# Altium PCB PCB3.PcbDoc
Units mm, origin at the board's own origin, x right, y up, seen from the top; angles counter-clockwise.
Board outline 101.6 x 53.34 mm, 4 copper layers (TOP, GND, SIG, BOTTOM), stack 1.586 mm thick; 108 components, 243 nets, 903 pads, 0 vias.
Unrouted connection lines stored in the file: 26.
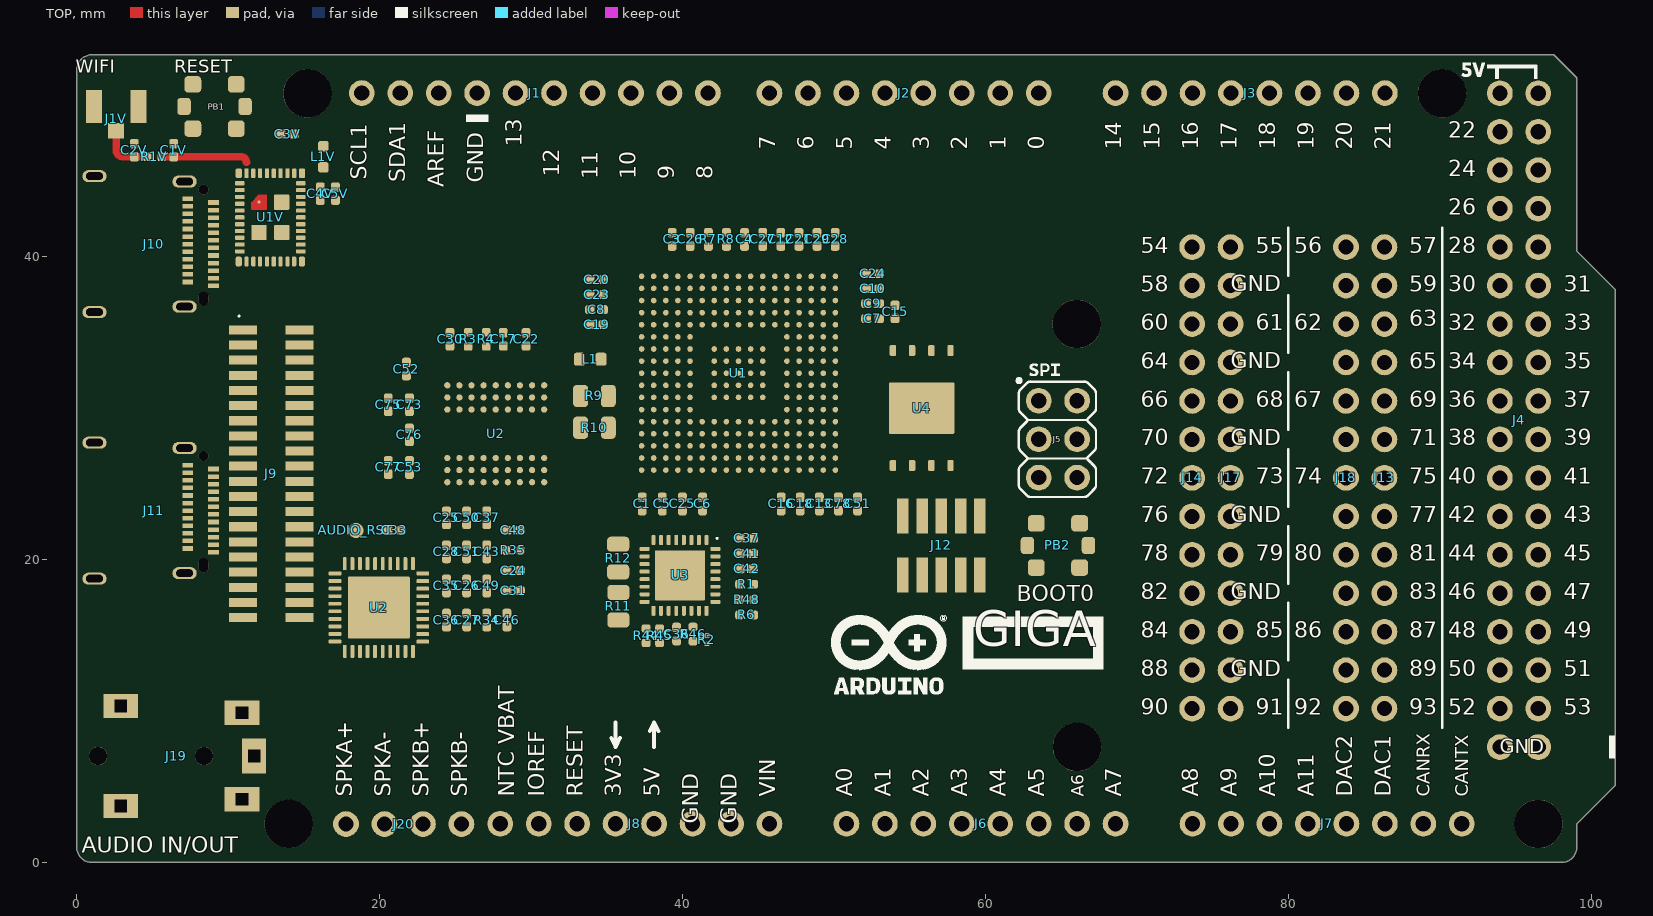
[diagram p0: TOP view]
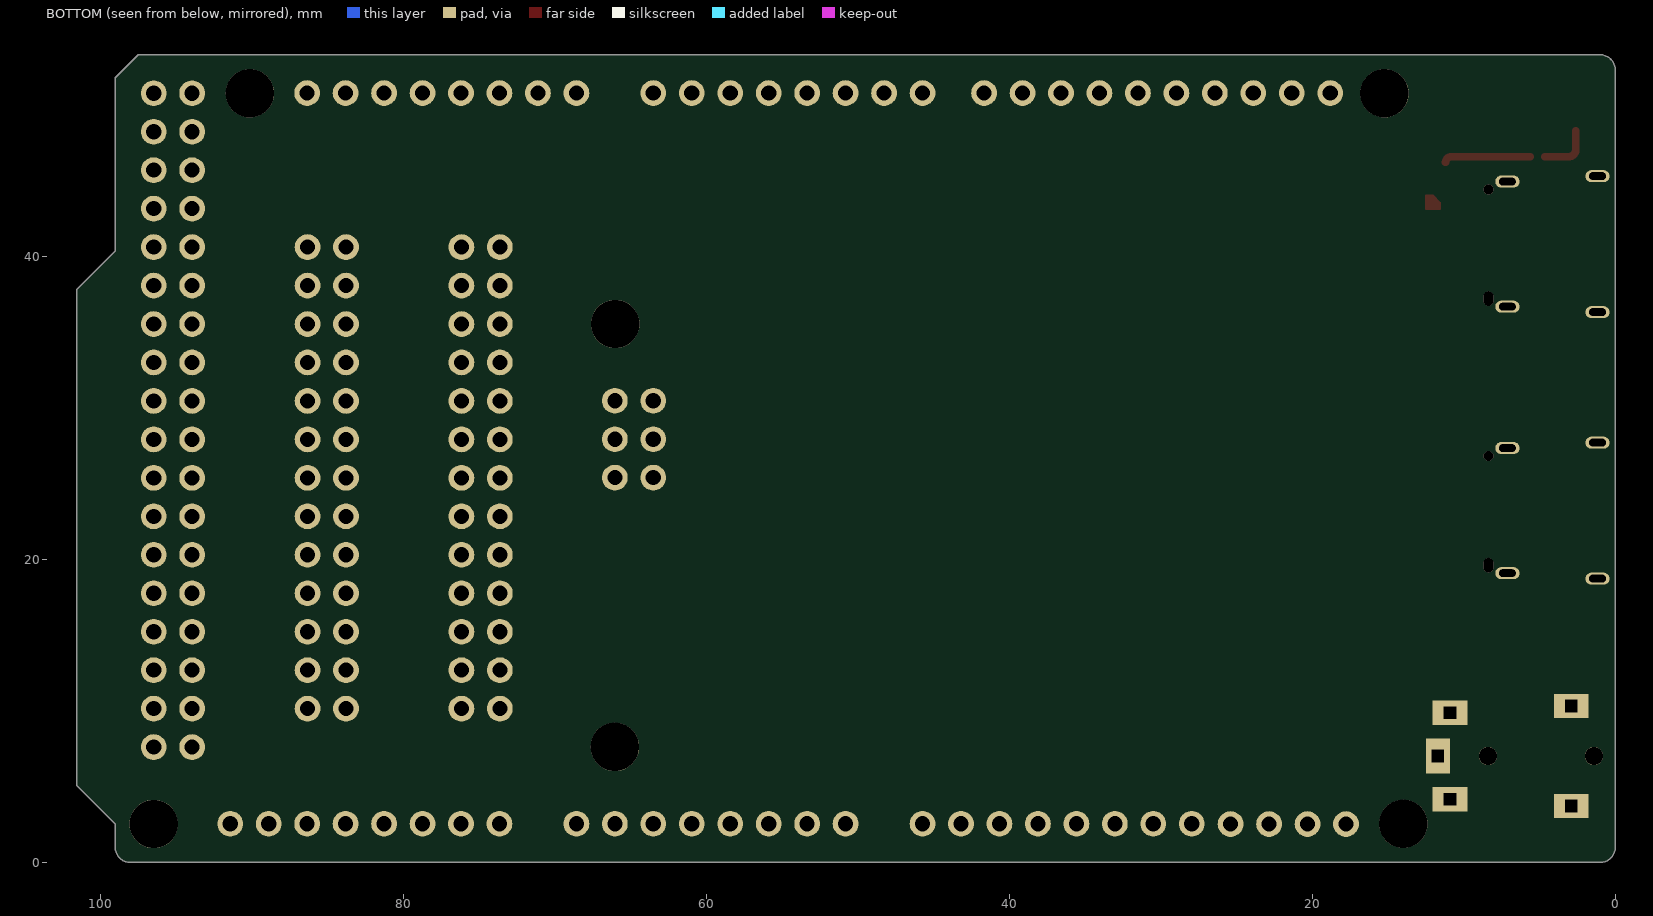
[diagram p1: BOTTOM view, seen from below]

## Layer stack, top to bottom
Top Solder: solder mask 0.0102, Solder Resist, Dk 3.5
TOP: signal copper 0.018
Dielectric 1: prepreg 0.14, PP-014, Dk 4.2
GND: signal copper 0.035
Dielectric2: core 1.2, FR-4, Dk 4.8
SIG: signal copper 0.035
Dielectric3: prepreg 0.14, PP-014, Dk 4.2
BOTTOM: signal copper 0.018
Bottom Solder: solder mask 0.0102, Solder Resist, Dk 3.5

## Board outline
0,1 0,52.34 cw(c1,52.34) 1,53.34 97.536,53.34 99.06,51.816 99.06,40.386 101.6,37.846 101.6,5.08 99.06,2.54 99.06,1 cw(c98.06,1) 98.06,0 1,0 cw(c1,1)

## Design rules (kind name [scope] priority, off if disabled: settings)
BoardOutlineClearance Silks [(OnLayer('Top Overlay') OR OnLayer('Bottom Overlay'))] p1: gap=0.1 ignorepadtopadclearanceinfootprint=FALSE
BoardOutlineClearance [All] p2: gap=0.3 ignorepadtopadclearanceinfootprint=FALSE
Clearance COPPER_0.3mm [All] p1: gap=0.127 ignorepadtopadclearanceinfootprint=FALSE except(0.3: Arc-Fill Arc-Poly Arc-Region Track-Fill Track-Poly Track-Region SMDPad-Fill SMDPad-Poly SMDPad-Region THPad-Fill THPad-Poly THPad-Region Via-Fill Via-Poly Via-Region Fill-Fill Fill-Poly Fill-Region Poly-Poly Poly-Region Region-Region)
Clearance "Generic clearance 0.127mm" [All] p2: gap=0.127 ignorepadtopadclearanceinfootprint=FALSE
ComponentClearance [All] p1: gap=0.2 collisioncheckmode=3 verticalgap=0 showdistances=TRUE
DiffPairsRouting USB [InDifferentialPairClass('USB')] p1: maxlimit=0.254 minlimit=0.15 mostfreqgap=0.254 toplayer_maxgap=0.15 toplayer_prefgap=0.15 toplayer_minwidth=0.15 toplayer_maxwidth=0.21 toplayer_prefwidth=0.2 midlayer2_mingap=0.24 midlayer2_maxgap=0.24 midlayer2_prefgap=0.24 midlayer2_minwidth=0.15 midlayer2_maxwidth=0.15 midlayer2_prefwidth=0.15 bottomlayer_maxgap=0.15 bottomlayer_prefgap=0.15 bottomlayer_minwidth=0.15 bottomlayer_maxwidth=0.21 bottomlayer_prefwidth=0.2 impedanceprofiledriven=TRUE impedanceprofileid={E6B00C31-4C8E-439C-824F-D2B2CDC26F9C} impedanceprofilevalue=90.000000 maxuncoupledlength=12.7
Height [All] p1: minheight=0 maxheight=30 prefheight=12.7
HoleSize [All] p1: absolutevalues=TRUE maxlimit=20 minlimit=0.3 maxpercent=80.000 minpercent=20.000
HoleToHoleClearance [All] p1: gap=0.25 allowstackedmicrovias=FALSE
MinimumAnnularRing [All] p1: minimumring=0.15
PlaneConnect [All] p1: pad.planeconnectstyle=Relief pad.reliefexpansion=0.508 pad.reliefentries=4 pad.reliefconductorwidth=0.254 pad.reliefairgap=0.254 via.planeconnectstyle=Direct via.reliefexpansion=0.508 via.reliefentries=4 via.reliefconductorwidth=0.254 via.reliefairgap=0.254
PolygonConnect [All] p1: thpad.connectstyle=Relief thpad.reliefconductorwidth=0.2 thpad.reliefentries=4 thpad.polygonreliefangle="90 Angle" thpad.airgapwidth=0.254 smdpad.connectstyle=Relief smdpad.reliefconductorwidth=0.2 smdpad.reliefentries=4 smdpad.polygonreliefangle="90 Angle" smdpad.airgapwidth=0.254 via.connectstyle=Direct via.reliefconductorwidth=0.254 via.reliefentries=4 via.polygonreliefangle="90 Angle" via.airgapwidth=0.254
RoomDefinition AUDIO [InComponentClass('AUDIO')] p1: confinementstyle=ConfineIn formatcopy=TRUE lockcomponents=FALSE outline 102.7,0.5 179.2,0.5 179.2,30 102.7,30
RoomDefinition Wifi [InComponentClass('Wifi')] p2: confinementstyle=ConfineIn formatcopy=TRUE lockcomponents=FALSE outline -40.4,-40.4 10.4,-40.4 10.4,-15 -40.4,-15
RoomDefinition TOP [InComponentClass('TOP')] p3: confinementstyle=ConfineIn formatcopy=TRUE lockcomponents=FALSE outline 102.7,1.5 112.4,1.5 112.4,12.5 102.7,12.5
RoomDefinition HEADERS [InComponentClass('HEADERS')] p4: confinementstyle=ConfineIn formatcopy=TRUE lockcomponents=FALSE outline 103.6,3.6 145.6,3.6 145.6,51.6 103.6,51.6
RoomDefinition STM32H747 [InComponentClass('STM32H747')] p5: confinementstyle=ConfineIn formatcopy=TRUE lockcomponents=FALSE outline 57.6,-10.4 61.6,-10.4 61.6,-6.4 57.6,-6.4
RoutingVias StandardVias [All] p1: holewidth=0.2 width=0.4 viastyle="Through Hole" minholewidth=0.2 minwidth=0.4 maxholewidth=0.2 maxwidth=0.4
SMDToCorner [All] p1: distance=39370
SilkToSilkClearance [All] p1: silktosilkclearance=0.2
SilkToSolderMaskClearance [IsPad] p1: minsilkscreentomaskgap=0.15 clearancetoexposedcopper=TRUE
SolderMaskExpansion VIAtented [IsVia] p1: expansion=0.102 istentingtop=TRUE
SolderMaskExpansion [All] p2: expansion=0.05 istentingtop=FALSE
UnRoutedNet [All] p1: checkbadconnections=TRUE
ViasUnderSMD [All] p1: allowed=FALSE
Width StandardTraces [All] p1: maxlimit=5 minlimit=0.127 preferedwidth=0.15
21 further rules are at their usual default settings.

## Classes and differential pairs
component class AUDIO: J19
net class "50 ohm": NetC1V_1 NetC2V_1
component class Wifi: C1V C2V C3V C4V C5V J1V L1V R1V R18 U1V
component class TOP: PB1 PB2
component class HEADERS: J1 J2 J3 J4 J5 J6 J7 J8 J13 J14 J17 J18 J20

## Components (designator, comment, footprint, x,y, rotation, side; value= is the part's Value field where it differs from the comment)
AUDIO_RST "CMP-018-0005-A.3" TP-1.00MM 18.437,21.925 r180 top
C1 "CBR04C220F5GAC" CAP-0402 37.34,23.675 r90 top value=22pF
C1V "DNP" CAP-0402 6.4,47.035 r90 top
C2V "DNP" CAP-0402 3.8,47.035 r90 top
C3 "GRM155R60J106ME05D" CAP-0402 39.319,41.145 r270 top value=10µF
C3V "GRM155R60J225KE95D" CAP-0402 13.919,48.102 r180 top value=2.2µF
C4 "GRM155R60J225KE95D" CAP-0402 44.104,41.145 r270 top value=2.2µF
C4V "GRM155R60J475ME47D" CAP-0402 16.084,44.167 r270 top value=4.7µF
C5 "GRM155R60J225KE95D" CAP-0402 38.67,23.675 r90 top value=2.2µF
C5V "GRM155R60J475ME47D" CAP-0402 17.084,44.167 r270 top value=4.7µF
C6 "GRM155R60J225KE95D" CAP-0402 41.33,23.675 r90 top value=2.2µF
C7 "GRM155R61H104KE19D" CAP-0402 52.557,35.913 r0 top value=100nF
C8 "GRM155R61H104KE19D" CAP-0402 34.325,36.51 r0 top value=100nF
C9 "GRM155R61H104KE19D" CAP-0402 52.557,36.903 r0 top value=100nF
C10 "GRM155R61H104KE19D" CAP-0402 52.557,37.893 r0 top value=100nF
C12 "CBR04C220F5GAC" CAP-0402 46.496,41.145 r270 top value=22pF
C13 "GRM155R61H104KE19D" CAP-0402 49.041,23.675 r270 top value=100nF
C15 "GRM155R61H104KE19D" CAP-0402 54.039,36.36 r90 top value=100nF
C16 "GRM155R61H104KE19D" CAP-0402 46.52,23.675 r270 top value=100nF
C17 "GRM155R61H104KE19D" CAP-0402 28.169,34.545 r90 top value=100nF
C18 "GRM155R61H104KE19D" CAP-0402 47.781,23.675 r270 top value=100nF
C19 "GRM155R61H104KE19D" CAP-0402 34.325,35.52 r0 top value=100nF
C20 "GRM155R61H104KE19D" CAP-0402 34.325,38.49 r0 top value=100nF
C21 "GRM155R61H104KE19D" CAP-0402 47.692,41.145 r270 top value=100nF
C22 "GRM155R61H104KE19D" CAP-0402 29.669,34.545 r90 top value=100nF
C23 "GRM155R61H104KE19D" CAP-0402 34.325,37.5 r0 top value=100nF
C24 "GRM155R61H104KE19D" CAP-0402 52.557,38.883 r0 top value=100nF
C24 "C0402C105K8PACTU" CAP-0402 28.835,19.28 r180 top value=1µF
C25 "GRM155R60J225KE95D" CAP-0402 40,23.675 r90 top value=2.2µF
C25 "C0402C104K4RACTU" CAP-0402 24.416,22.76 r90 top value=100nF
C26 "GRM155R60J225KE95D" CAP-0402 40.515,41.145 r270 top value=2.2µF
C26 "C0402C104K4RACTU" CAP-0402 25.746,18.26 r90 top value=100nF
C27 "GRM155R60J225KE95D" CAP-0402 45.3,41.145 r270 top value=2.2µF
C27 "C0402C104K4RACTU" CAP-0402 25.746,16.01 r90 top value=100nF
C28 "GRM155R61H104KE19D" CAP-0402 50.085,41.145 r270 top value=100nF
C28 "C0402C105K8PACTU" CAP-0402 24.416,20.51 r90 top value=1µF
C29 "GRM155R61H104KE19D" CAP-0402 48.889,41.145 r270 top value=100nF
C30 "GRM155R60J106ME05D" CAP-0402 24.648,34.545 r270 top value=10µF
C31 "C0402C105K8PACTU" CAP-0402 28.835,17.95 r180 top value=1µF
C33 "C0402C105K8PACTU" CAP-0402 20.977,21.925 r180 top value=1µF
C35 "C0402C104K4RACTU" CAP-0402 24.416,18.26 r90 top value=100nF
C36 "GRM155R61H104KE19D" CAP-0402 39.615,15.085 r90 top value=100nF
C36 "C0402C104K4RACTU" CAP-0402 24.416,16.01 r90 top value=100nF
C37 "GRM155R61H104KE19D" CAP-0402 44.235,21.41 r180 top value=100nF
C37 "C0402C104K4RACTU" CAP-0402 27.076,22.76 r90 top value=100nF
C41 "GRM155R61H104KE19D" CAP-0402 44.235,20.397 r180 top value=100nF
C42 "GRM155R61H104KE19D" CAP-0402 44.235,19.383 r180 top value=100nF
C43 "C0402C104K4RACTU" CAP-0402 27.076,20.51 r90 top value=100nF
C46 "GRM1555C1H151FA01D" CAP-0402 28.406,16.01 r90 top value=150pF
C48 "C0402C104K4RACTU" CAP-0402 28.835,21.94 r180 top value=100nF
C49 "C0402C105K8PACTU" CAP-0402 27.076,18.26 r90 top value=1µF
C50 "GRM1555C1H151FA01D" CAP-0402 25.746,22.76 r90 top value=150pF
C51 "GRM155R61H104KE19D" CAP-0402 51.563,23.675 r270 top value=100nF
C51 "C0402C104K4RACTU" CAP-0402 25.746,20.51 r90 top value=100nF
C52 "GRM155R61H104KE19D" CAP-0402 21.772,32.585 r90 top value=100nF
C53 "GRM155R61H104KE19D" CAP-0402 21.972,26.085 r270 top value=100nF
C73 "GRM155R61H104KE19D" CAP-0402 21.972,30.23 r90 top value=100nF
C75 "GRM155R61H104KE19D" CAP-0402 20.572,30.23 r270 top value=100nF
C76 "GRM155R61H104KE19D" CAP-0402 21.972,28.24 r90 top value=100nF
C77 "GRM155R61H104KE19D" CAP-0402 20.572,26.085 r90 top value=100nF
C78 "GRM155R61H104KE19D" CAP-0402 50.302,23.675 r270 top value=100nF
J1 "HEADER TH 2.54mm VERT. 1x010POS" "PIN HEADER 2.54mm VERT. 1x10POS" 30.252,50.813 r0 top
J1V "U.FL-R-SMT-1(60)" U.FL-R-SMT-1(60)-1 2.6,49.925 r0 top
J2 "HEADER TH 2.54mm VERT. 1x008POS" "PIN HEADER 2.54mm VERT. 1x8POS" 54.636,50.813 r0 top
J3 "HEADER TH 2.54mm VERT. 1x008POS" "PIN HEADER 2.54mm VERT. 1x8POS" 77.496,50.813 r0 top
J4 "HEADER TH 2.54mm VERT. 2x018POS" "PIN HEADER 2.54mm VERT. 2x6POS" 95.25,29.209 r270 top
J5 "HEADER TH 2.54mm VERT. 2x003POS" "HEADER TH 2.54mm VERT. 2x003POS-Footprint-1" 64.796,27.953 r270 top
J6 "HEADER TH 2.54mm VERT. 1x008POS" "PIN HEADER 2.54mm VERT. 1x8POS" 59.716,2.553 r0 top
J7 "HEADER TH 2.54mm VERT. 1x008POS" "PIN HEADER 2.54mm VERT. 1x8POS" 82.576,2.553 r0 top
J8 "HEADER TH 2.54mm VERT. 1x008POS" "PIN HEADER 2.54mm VERT. 1x8POS" 36.856,2.553 r0 top
J9 "2-1734248-0" 2-1734248-0-Footprint-1 12.884,25.67 r0 top (schematic designator J4)
J10 "12401598E4#2A" 12401598E4#2A 5.1,40.835 r270 top (schematic designator J1)
J11 "12401598E4#2A" 12401598E4#2A 5.1,23.235 r270 top (schematic designator J1)
J12 "FTSH-105-01-F-DV" FTSH-105-01-F-DV-Footprint-1 57.1,20.933 r180 top
J13 "HEADER TH 2.54mm VERT. 1x013POS" "PIN HEADER 2.54mm VERT. 1x13POS" 86.36,25.399 r270 top
J14 "HEADER TH 2.54mm VERT. 1x013POS" "PIN HEADER 2.54mm VERT. 1x13POS" 73.66,25.399 r270 top
J17 "HEADER TH 2.54mm VERT. 1x013POS" "PIN HEADER 2.54mm VERT. 1x13POS" 76.2,25.399 r270 top
J18 "HEADER TH 2.54mm VERT. 1x013POS" "PIN HEADER 2.54mm VERT. 1x13POS" 83.82,25.399 r270 top
J19 "54-00174" 54-00174-Footprint-1 11.71,7.03 r0 top
J20 "HEADER TH 2.54mm VERT. 1x004POS" "PIN HEADER 2.54mm VERT. 1x4POS-Footprint-1" 21.59,2.539 r0 top
L1 "FBMJ1608HM180NTR" L-0603 33.91,33.24 r0 top
L1V "LQM18PN2R2MGHD" FP-LQM18PN_GH-IPC_C 16.284,46.602 r270 top value=2.2uH
PB1 "PTS820J25KSMTRLFS" C&K_PTS820_NO_HOLES-1 9.1,49.925 r180 top
PB2 "PTS820J25KSMTRLFS" C&K_PTS820_NO_HOLES-1 64.796,20.933 r180 top
R1 "CRCW0402100KFKEDC" RES-0402 44.235,18.37 r0 top value=100k
R1V "CRCW04020000Z0EDC" RES-0402 5.125,46.6 r180 top value=0
R2 "RC0201FR-078K06L" RES-0201 41.615,14.715 r270 top value=8.06k
R3 "CRCW04020000Z0EDC" RES-0402 25.848,34.545 r90 top value=0
R4 "CRCW0402100KFKEDC" RES-0402 27.048,34.545 r90 top value=100k
R6 "CRCW0402100KFKEDC" RES-0402 44.235,16.343 r180 top value=100k
R7 "CRCW04020000Z0EDC" RES-0402 41.711,41.145 r270 top value=0
R8 "CRCW04020000Z0EDC" RES-0402 42.908,41.145 r270 top value=0
R9 "CRCW08050000Z0EB" RES-0805 34.185,30.81 r180 top value=0
R10 "CRCW08050000Z0EB" RES-0805 34.185,28.71 r180 top value=0
R11 "CRCW08050000Z0EB" RES-0805 35.769,16.92 r90 top value=0
R12 "CRCW08050000Z0EB" RES-0805 35.751,20.101 r270 top value=0
R34 "CRCW04022K00JNED" RES-0402 27.076,16.01 r90 top value=2k
R35 "CRCW04022K00JNED" RES-0402 28.835,20.61 r180 top value=2k
R44 "CRCW04020000Z0EDC" RES-0402 37.6,14.97 r270 top value=0
R45 "CRCW04020000Z0EDC" RES-0402 38.492,14.97 r270 top value=0
R46 "CRCW040210K0FKED" RES-0402 40.7,15.085 r270 top value=10k
R48 "CRCW0402100KFKEDC" RES-0402 44.235,17.357 r0 top value=100k
U1 "STM32H747XIH6" STM32H747XIH6-Footprint-1 43.7,32.31 r270 top
U1V "LBEE5KL1DX-883" LBEE5KL1DX-883 12.784,42.602 r270 top
U2 "AS4C4M16SA-6BIN" AS4C4M16SA-7BCN-Footprint-1 27.669,28.31 r0 top
U2 "CS42L52-CNZ" QFN127P600-8N 19.951,16.835 r90 top
U3 "USB3320C-EZK-TR" USB3320C-EZK-Footprint-1 39.838,18.958 r180 top
U4 "MX25L12833FZ2I-10G" WSON8-1 55.8,30.01 r180 top

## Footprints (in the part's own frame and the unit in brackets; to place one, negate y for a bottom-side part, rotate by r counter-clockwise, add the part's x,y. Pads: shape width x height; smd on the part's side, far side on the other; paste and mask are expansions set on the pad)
2-1734248-0-Footprint-1 [mm]
  rect 1.85x0.6 smd: 1(-1.9,9.5) 2(-1.9,8.5) 3(-1.9,7.5) 4(-1.9,6.5) 5(-1.9,5.5) 6(-1.9,4.5) 7(-1.9,3.5) 8(-1.9,2.5) 9(-1.9,1.5) 10(-1.9,0.5) 11(-1.9,-0.5) 12(-1.9,-1.5) 13(-1.9,-2.5) 14(-1.9,-3.5) 15(-1.9,-4.5) 16(-1.9,-5.5) 17(-1.9,-6.5) 18(-1.9,-7.5) 19(-1.9,-8.5) 20(-1.9,-9.5) 21(1.825,-9.5) 22(1.825,-8.5) 23(1.825,-7.5) 24(1.825,-6.5) 25(1.825,-5.5) 26(1.825,-4.5) 27(1.825,-3.5) 28(1.825,-2.5) 29(1.825,-1.5) 30(1.825,-0.5) 31(1.825,0.5) 32(1.825,1.5) 33(1.825,2.5) 34(1.825,3.5) 35(1.825,4.5) 36(1.825,5.5) 37(1.825,6.5) 38(1.825,7.5) 39(1.825,8.5) 40(1.825,9.5)
  silkscreen extent -2.21,10.36 -2.11,10.46, body extent -2.4,-13.7 2.45,13.7, height 5.63
54-00174-Footprint-1 [mm]
  rect 1.6x2.3 hole 0.8 square unplated: 1(0,0)
  rect 2.3x1.6 hole 0.8 square unplated: 2(-0.8,2.85) 3(-0.8,-2.85) 4(-8.8,-3.3) 4(-8.8,3.3)
  round 1.2 hole 1.2 unplated mask+0.2: NC1(-3.3,0) NC2(-10.3,0)
  body extent -14.74,-3.5 0.26,3.6, height 6.13
12401598E4#2A [mm]
  oval 1x1.8 on Top Paste: 0(-4.499,-3.932) 0(-4.131,2.023) 0(4.131,2.026) 0(4.461,-3.925)
  round 0.65 hole 0.65 unplated mask+0.05: 0(-3.6,3.27)
  oval 0.95x0.65 hole 0.65 slot 0.95 at 0 deg unplated mask+0: 0(3.6,3.27)
  rect 0.3x0.7 smd mask+0.04: A1(-2.75,3.93) A2(-2.25,3.93) A3(-1.75,3.93) A4(-1.25,3.93) A5(-0.75,3.93) A6(-0.25,3.93) A7(0.25,3.93) A8(0.75,3.93) A9(1.25,3.93) A10(1.75,3.93) B1(2.5,2.23) B2(2,2.23) B3(1.5,2.23) B4(1,2.23) B5(0.5,2.23) B6(0,2.23) B7(-0.5,2.23) B8(-1,2.23) B9(-1.5,2.23) B10(-2,2.23) B11(-2.5,2.23) B12(-3,2.23)
  rect 0.3x0.7 smd mask+0.03: A11(2.25,3.93) A12(2.75,3.93)
  oval 0.8x1.6 hole 0.5 slot 1.1 at 90 deg: "SHIELD 1"(-4.13,2.02) "SHIELD 2"(4.13,2.02) "SHIELD 3"(-4.49,-3.93) "SHIELD 4"(4.49,-3.93)
  body extent -4.6,-6.3 4.6,4.25, height 3.3
AS4C4M16SA-7BCN-Footprint-1 [mm]
  round 0.41 smd: A1(-3.2,-3.2) A2(-3.2,-2.4) A3(-3.2,-1.6) A7(-3.2,1.6) A8(-3.2,2.4) A9(-3.2,3.2) B1(-2.4,-3.2) B2(-2.4,-2.4) B3(-2.4,-1.6) B7(-2.4,1.6) B8(-2.4,2.4) B9(-2.4,3.2) C1(-1.6,-3.2) C2(-1.6,-2.4) C3(-1.6,-1.6) C7(-1.6,1.6) C8(-1.6,2.4) C9(-1.6,3.2) D1(-0.8,-3.2) D2(-0.8,-2.4) D3(-0.8,-1.6) D7(-0.8,1.6) D8(-0.8,2.4) D9(-0.8,3.2) E1(0,-3.2) E2(0,-2.4) E3(0,-1.6) E7(0,1.6) E8(0,2.4) E9(0,3.2) F1(0.8,-3.2) F2(0.8,-2.4) F3(0.8,-1.6) F7(0.8,1.6) F8(0.8,2.4) F9(0.8,3.2) G1(1.6,-3.2) G2(1.6,-2.4) G3(1.6,-1.6) G7(1.6,1.6) G8(1.6,2.4) G9(1.6,3.2) H1(2.4,-3.2) H2(2.4,-2.4) H3(2.4,-1.6) H7(2.4,1.6) H8(2.4,2.4) H9(2.4,3.2) J1(3.2,-3.2) J2(3.2,-2.4) J3(3.2,-1.6) J7(3.2,1.6) J8(3.2,2.4) J9(3.2,3.2)
  body extent -4,-4 4,4, height 1.15
C&K_PTS820_NO_HOLES-1 [mm]
  rrect49% 0.89x1.12 smd: 5(-2.015,0) 6(2.015,0)
  rrect46% 1.11x1.09 smd: PAD(-1.434,1.46) PAD(-1.434,-1.46) PAD(1.434,1.46) PAD(1.434,-1.46)
  body extent -2.25,-1.45 2.25,1.45, height 2
CAP-0402 [mm] "Chip Capacitor, 2-Leads, Body  0402 (in) 1005 (mm), IPC Medium Density"
  rrect52% 0.63x0.58 smd mask+0: 1(-0.435,0) 2(0.435,0)
  body extent -0.5,-0.25 0.5,0.25, height 0.5
FP-LQM18PN_GH-IPC_C [mm]
  rrect50% 0.7x0.7 smd: 1(-0.7,0) 2(0.7,0)
  body extent -0.8,-0.4 0.8,0.4, height 1
FTSH-105-01-F-DV-Footprint-1 [mm]
  rect 0.76x2.3 smd: 1(-2.54,-1.95) 2(-2.54,1.95) 3(-1.27,-1.95) 4(-1.27,1.95) 5(0,-1.95) 6(0,1.95) 7(1.27,-1.95) 8(1.27,1.95) 9(2.54,-1.95) 10(2.54,1.95)
  body extent -3.17,-2.92 3.17,2.92, height 5.98
"HEADER TH 2.54mm VERT. 2x003POS-Footprint-1" [mm]
  round 1.7 hole 1 mask+0.2: 1(-2.54,-1.27) 2(-2.54,1.27) 3(0,-1.27) 4(0,1.27) 5(2.54,-1.27) 6(2.54,1.27)
L-0603 [mm] "Chip Inductor - Body 0603 imperial,1.6x0.8mm, IPC High Density"
  rrect51% 0.75x0.87 smd mask+0: 1(-0.71,0) 2(0.71,0)
  body extent -0.8,-0.4 0.8,0.4, height 0.8
LBEE5KL1DX-883 [mm]
  rrect50% 0.28x0.64 smd mask+0.05: 1(-2.25,-2.015) 2(-1.8,-2.015) 3(-1.35,-2.015) 4(-0.9,-2.015) 5(-0.45,-2.015) 6(0,-2.015) 7(0.45,-2.015) 8(0.9,-2.015) 9(1.35,-2.015) 10(1.8,-2.015) 11(2.25,-2.015) 22(2.25,2.015) 23(1.8,2.015) 24(1.35,2.015) 25(0.9,2.015) 26(0.45,2.015) 27(0,2.015) 28(-0.45,2.015) 29(-0.9,2.015) 30(-1.35,2.015) 31(-1.8,2.015) 32(-2.25,2.015)
  rrect50% 0.64x0.4 smd mask+0.05: 12(2.915,-2.087) 21(2.915,2.087) 33(-2.915,2.087) 42(-2.915,-2.087)
  rrect50% 0.64x0.28 smd mask+0.05: 13(2.915,-1.575) 14(2.915,-1.125) 15(2.915,-0.675) 16(2.915,-0.225) 17(2.915,0.225) 18(2.915,0.675) 19(2.915,1.125) 20(2.915,1.575) 34(-2.915,1.575) 35(-2.915,1.125) 36(-2.915,0.675) 37(-2.915,0.225) 38(-2.915,-0.225) 39(-2.915,-0.675) 40(-2.915,-1.125) 41(-2.915,-1.575)
  round 0.2 smd paste+0 mask+0.05: 43(-1,-0.75)
  rrect10% 1x1 smd mask+0.05: 44(1,-0.75) 45(-1,0.75) 46(1,0.75)
  TOP region: -1.485,-0.765 -1.496,-0.748 -1.5,-0.729 -1.5,-0.729 -1.5,-0.3 -1.496,-0.281 -1.485,-0.265 -1.469,-0.254 -1.45,-0.25 -1.45,-0.25 -0.55,-0.25 -0.531,-0.254 -0.515,-0.265 -0.504,-0.281 -0.5,-0.3 -0.5,-0.3 -0.5,-1.2 -0.504,-1.219 -0.515,-1.235 -0.531,-1.246 -0.55,-1.25 -0.55,-1.25 -0.979,-1.25 -0.998,-1.246 -1.015,-1.235 -1.015,-1.235
  body extent -3.47,-2.57 3.48,2.58, height 1.1
"PIN HEADER 2.54mm VERT. 1x4POS-Footprint-1" [mm]
  round 1.7 hole 1 mask+0.2: 1(-3.81,0) 2(-1.27,0) 3(1.27,0) 4(3.81,0)
"PIN HEADER 2.54mm VERT. 1x8POS" [mm]
  round 1.7 hole 1 mask+0.2: 1(-8.89,0) 2(-6.35,0) 3(-3.81,0) 4(-1.27,0) 5(1.27,0) 6(3.81,0) 7(6.35,0) 8(8.89,0)
"PIN HEADER 2.54mm VERT. 1x10POS" [mm]
  round 1.7 hole 1 mask+0.2: 1(-11.43,0) 2(-8.89,0) 3(-6.35,0) 4(-3.81,0) 5(-1.27,0) 6(1.27,0) 7(3.81,0) 8(6.35,0) 9(8.89,0) 10(11.43,0)
"PIN HEADER 2.54mm VERT. 1x13POS" [mm]
  round 1.7 hole 1 mask+0.2: 1(-15.24,0) 2(-12.7,0) 3(-10.16,0) 4(-7.62,0) 5(-5.08,0) 6(-2.54,0) 7(0,0) 8(2.54,0) 9(5.08,0) 10(7.62,0) 11(10.16,0) 12(12.7,0) 13(15.24,0)
"PIN HEADER 2.54mm VERT. 2x6POS" [mm]
  round 1.7 hole 1 mask+0.2: 1(-21.59,-1.27) 2(-21.59,1.27) 3(-19.05,-1.27) 4(-19.05,1.27) 5(-16.51,-1.27) 6(-16.51,1.27) 7(-13.97,-1.27) 8(-13.97,1.27) 9(-11.43,-1.27) 10(-11.43,1.27) 11(-8.89,-1.27) 12(-8.89,1.27) 13(-6.35,-1.27) 14(-6.35,1.27) 15(-3.81,-1.27) 16(-3.81,1.27) 17(-1.27,-1.27) 18(-1.27,1.27) 19(1.27,-1.27) 20(1.27,1.27) 21(3.81,-1.27) 22(3.81,1.27) 23(6.35,-1.27) 24(6.35,1.27) 25(8.89,-1.27) 26(8.89,1.27) 27(11.43,-1.27) 28(11.43,1.27) 29(13.97,-1.27) 30(13.97,1.27) 31(16.51,-1.27) 32(16.51,1.27) 33(19.05,-1.27) 34(19.05,1.27) 35(21.59,-1.27) 36(21.59,1.27)
QFN127P600-8N [mm]
  rrect50% 0.85x0.25 smd mask+0.05: 1(-2.9,2.25) 2(-2.9,1.75) 3(-2.9,1.25) 4(-2.9,0.75) 5(-2.9,0.25) 6(-2.9,-0.25) 7(-2.9,-0.75) 8(-2.9,-1.25) 9(-2.9,-1.75) 10(-2.9,-2.25) 21(2.9,-2.25) 22(2.9,-1.75) 23(2.9,-1.25) 24(2.9,-0.75) 25(2.9,-0.25) 26(2.9,0.25) 27(2.9,0.75) 28(2.9,1.25) 29(2.9,1.75) 30(2.9,2.25)
  rrect50% 0.25x0.85 smd mask+0.05: 11(-2.25,-2.9) 12(-1.75,-2.9) 13(-1.25,-2.9) 14(-0.75,-2.9) 15(-0.25,-2.9) 16(0.25,-2.9) 17(0.75,-2.9) 18(1.25,-2.9) 19(1.75,-2.9) 20(2.25,-2.9) 31(2.25,2.9) 32(1.75,2.9) 33(1.25,2.9) 34(0.75,2.9) 35(0.25,2.9) 36(-0.25,2.9) 37(-0.75,2.9) 38(-1.25,2.9) 39(-1.75,2.9) 40(-2.25,2.9)
  rrect5% 4.1x4.1 smd paste-5 mask+0.05: 41(0,0)
  body extent -3,-3 3,3, height 1
RES-0201 [mm] "Chip Resistor, 2-Leads, Body 0201 (in) 0603 (mm) IPC Medium Density"
  rrect52% 0.31x0.34 smd mask+0: 1(-0.275,0) 2(0.275,0)
  body extent -0.3,-0.15 0.3,0.15, height 0.24
RES-0402 [mm] "Chip Resistor, 2-Leads, Body  0402 (in) 1005 (mm), IPC Medium Density"
  rrect51% 0.55x0.58 smd mask+0: 1(-0.475,0) 2(0.475,0)
  body extent -0.5,-0.25 0.5,0.25, height 0.34
RES-0805 [mm] "Chip Resistor - Body 0805 imperial, 2.0x1.2mm, IPC Medium Density"
  rrect51% 0.99x1.47 smd paste-1.47 mask+0: 1(-0.915,0) 2(0.915,0)
  body extent -1,-0.62 1,0.63, height 0.58
STM32H747XIH6-Footprint-1 [mm]
  round 0.37 smd: A1(-6.4,-6.4) A2(-6.4,-5.6) A3(-6.4,-4.8) A4(-6.4,-4) A5(-6.4,-3.2) A6(-6.4,-2.4) A7(-6.4,-1.6) A8(-6.4,-0.8) A9(-6.4,0) A10(-6.4,0.8) A11(-6.4,1.6) A12(-6.4,2.4) A13(-6.4,3.2) A14(-6.4,4) A15(-6.4,4.8) A16(-6.4,5.6) A17(-6.4,6.4) B1(-5.6,-6.4) B2(-5.6,-5.6) B3(-5.6,-4.8) B4(-5.6,-4) B5(-5.6,-3.2) B6(-5.6,-2.4) B7(-5.6,-1.6) B8(-5.6,-0.8) B9(-5.6,0) B10(-5.6,0.8) B11(-5.6,1.6) B12(-5.6,2.4) B13(-5.6,3.2) B14(-5.6,4) B15(-5.6,4.8) B16(-5.6,5.6) B17(-5.6,6.4) C1(-4.8,-6.4) C2(-4.8,-5.6) C3(-4.8,-4.8) C4(-4.8,-4) C5(-4.8,-3.2) C6(-4.8,-2.4) C7(-4.8,-1.6) C8(-4.8,-0.8) C9(-4.8,0) C10(-4.8,0.8) C11(-4.8,1.6) C12(-4.8,2.4) C13(-4.8,3.2) C14(-4.8,4) C15(-4.8,4.8) C16(-4.8,5.6) C17(-4.8,6.4) D1(-4,-6.4) D2(-4,-5.6) D3(-4,-4.8) D4(-4,-4) D5(-4,-3.2) D6(-4,-2.4) D7(-4,-1.6) D8(-4,-0.8) D9(-4,0) D10(-4,0.8) D11(-4,1.6) D12(-4,2.4) D13(-4,3.2) D14(-4,4) D15(-4,4.8) D16(-4,5.6) D17(-4,6.4) E1(-3.2,-6.4) E2(-3.2,-5.6) E3(-3.2,-4.8) E4(-3.2,-4) E5(-3.2,-3.2) E6(-3.2,-2.4) E7(-3.2,-1.6) E8(-3.2,-0.8) E9(-3.2,0) E10(-3.2,0.8) E11(-3.2,1.6) E12(-3.2,2.4) E13(-3.2,3.2) E14(-3.2,4) E15(-3.2,4.8) E16(-3.2,5.6) E17(-3.2,6.4) F1(-2.4,-6.4) F2(-2.4,-5.6) F3(-2.4,-4.8) F4(-2.4,-4) F5(-2.4,-3.2) F13(-2.4,3.2) F14(-2.4,4) F15(-2.4,4.8) F16(-2.4,5.6) F17(-2.4,6.4) G1(-1.6,-6.4) G2(-1.6,-5.6) G3(-1.6,-4.8) G4(-1.6,-4) G5(-1.6,-3.2) G7(-1.6,-1.6) G8(-1.6,-0.8) G9(-1.6,0) G10(-1.6,0.8) G11(-1.6,1.6) G13(-1.6,3.2) G14(-1.6,4) G15(-1.6,4.8) G16(-1.6,5.6) G17(-1.6,6.4) H1(-0.8,-6.4) H2(-0.8,-5.6) H3(-0.8,-4.8) H4(-0.8,-4) H5(-0.8,-3.2) H7(-0.8,-1.6) H8(-0.8,-0.8) H9(-0.8,0) H10(-0.8,0.8) H11(-0.8,1.6) H13(-0.8,3.2) H14(-0.8,4) H15(-0.8,4.8) H16(-0.8,5.6) H17(-0.8,6.4) J1(0,-6.4) J2(0,-5.6) J3(0,-4.8) J4(0,-4) J5(0,-3.2) J7(0,-1.6) J8(0,-0.8) J9(0,0) J10(0,0.8) J11(0,1.6) J13(0,3.2) J14(0,4) J15(0,4.8) J16(0,5.6) J17(0,6.4) K1(0.8,-6.4) K2(0.8,-5.6) K3(0.8,-4.8) K4(0.8,-4) K5(0.8,-3.2) K7(0.8,-1.6) K8(0.8,-0.8) K9(0.8,0) K10(0.8,0.8) K11(0.8,1.6) K13(0.8,3.2) K14(0.8,4) K15(0.8,4.8) K16(0.8,5.6) K17(0.8,6.4) L1(1.6,-6.4) L2(1.6,-5.6) L3(1.6,-4.8) L4(1.6,-4) L5(1.6,-3.2) L7(1.6,-1.6) L8(1.6,-0.8) L9(1.6,0) L10(1.6,0.8) L11(1.6,1.6) L13(1.6,3.2) L14(1.6,4) L15(1.6,4.8) L16(1.6,5.6) L17(1.6,6.4) M1(2.4,-6.4) M2(2.4,-5.6) M3(2.4,-4.8) M4(2.4,-4) M5(2.4,-3.2) M13(2.4,3.2) M14(2.4,4) M15(2.4,4.8) M16(2.4,5.6) M17(2.4,6.4) N1(3.2,-6.4) N2(3.2,-5.6) N3(3.2,-4.8) N4(3.2,-4) N5(3.2,-3.2) N6(3.2,-2.4) N7(3.2,-1.6) N8(3.2,-0.8) N9(3.2,0) N10(3.2,0.8) N11(3.2,1.6) N12(3.2,2.4) N13(3.2,3.2) N14(3.2,4) N15(3.2,4.8) N16(3.2,5.6) N17(3.2,6.4) P1(4,-6.4) P2(4,-5.6) P3(4,-4.8) P4(4,-4) P5(4,-3.2) P6(4,-2.4) P7(4,-1.6) P8(4,-0.8) P9(4,0) P10(4,0.8) P11(4,1.6) P12(4,2.4) P13(4,3.2) P14(4,4) P15(4,4.8) P16(4,5.6) P17(4,6.4) R1(4.8,-6.4) R2(4.8,-5.6) R3(4.8,-4.8) R4(4.8,-4) R5(4.8,-3.2) R6(4.8,-2.4) R7(4.8,-1.6) R8(4.8,-0.8) R9(4.8,0) R10(4.8,0.8) R11(4.8,1.6) R12(4.8,2.4) R13(4.8,3.2) R14(4.8,4) R15(4.8,4.8) R16(4.8,5.6) R17(4.8,6.4) T1(5.6,-6.4) T2(5.6,-5.6) T3(5.6,-4.8) T4(5.6,-4) T5(5.6,-3.2) T6(5.6,-2.4) T7(5.6,-1.6) T8(5.6,-0.8) T9(5.6,0) T10(5.6,0.8) T11(5.6,1.6) T12(5.6,2.4) T13(5.6,3.2) T14(5.6,4) T15(5.6,4.8) T16(5.6,5.6) T17(5.6,6.4) U1(6.4,-6.4) U2(6.4,-5.6) U3(6.4,-4.8) U4(6.4,-4) U5(6.4,-3.2) U6(6.4,-2.4) U7(6.4,-1.6) U8(6.4,-0.8) U9(6.4,0) U10(6.4,0.8) U11(6.4,1.6) U12(6.4,2.4) U13(6.4,3.2) U14(6.4,4) U15(6.4,4.8) U16(6.4,5.6) U17(6.4,6.4)
  body extent -7,-7 7,7, height 1.06
TP-1.00MM [mm]
  rrect100% 1x1 smd paste-2.54: X(0,0)
U.FL-R-SMT-1(60)-1 [mm]
  rect 1.05x2.2 smd paste-3: GND(-1.475,0) GND(1.475,0)
  rect 1.05x1 smd paste-3: SIG(0,-1.6)
  body extent -1.5,-1.55 1.5,1.55, height 1.25
USB3320C-EZK-Footprint-1 [mm]
  rrect54% 0.26x0.66 smd paste+0 mask+0: 1(-1.75,-2.335) 2(-1.25,-2.335) 3(-0.75,-2.335) 4(-0.25,-2.335) 5(0.25,-2.335) 6(0.75,-2.335) 7(1.25,-2.335) 8(1.75,-2.335) 17(1.75,2.335) 18(1.25,2.335) 19(0.75,2.335) 20(0.25,2.335) 21(-0.25,2.335) 22(-0.75,2.335) 23(-1.25,2.335) 24(-1.75,2.335)
  rrect54% 0.66x0.26 smd paste+0 mask+0: 9(2.335,-1.75) 10(2.335,-1.25) 11(2.335,-0.75) 12(2.335,-0.25) 13(2.335,0.25) 14(2.335,0.75) 15(2.335,1.25) 16(2.335,1.75) 25(-2.335,1.75) 26(-2.335,1.25) 27(-2.335,0.75) 28(-2.335,0.25) 29(-2.335,-0.25) 30(-2.335,-0.75) 31(-2.335,-1.25) 32(-2.335,-1.75)
  rrect3% 3.3x3.3 smd paste-3.3 mask+0: 33(0,0)
  silkscreen extent -2.5,-2.5 -2.4,-2.4, body extent -2.5,-2.5 2.5,2.5, height 0.85
WSON8-1 [mm]
  rrect52% 0.42x0.74 smd paste+0 mask+0: 1(-1.905,-3.795) 2(-0.635,-3.795) 3(0.635,-3.795) 4(1.905,-3.795) 5(1.905,3.795) 6(0.635,3.795) 7(-0.635,3.795) 8(-1.905,3.795)
  rrect3% 4.3x3.4 smd paste-4.3 mask+0: 9(0,0)
  body extent -3,-4 3,4, height 0.75

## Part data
AUDIO_RST: library part UT0013-A.2, "Test point 1.00mm"
C1 C12: library part C0028-A.9, "CAP CHIP 0402 22pF 50V C0G 1%", Case Code (Imperial)=0402, Case Code (Metric)=1005, Dielectric=C0G, Manufacturer=KEMET, Manufacturer 2=AVX, Manufacturer Part Number 2=04025U220FAT2A, Tolerance=1%, Voltage=50V
C1V C2V: library part UT0021-A.2, "DNP CAP 0402", Package=0402
C3 C30: library part C0091-A.8, "CAP CHIP 0402 10UF X5R 6.3V 20%", Case Code (Imperial)=0402, Case Code (Metric)=1005, Dielectric=X5R, Manufacturer=Murata, Tolerance=20%, Voltage=6.3V
C3V C4 C5 C6 C25 C26 C27: library part C0031-A.9, "CAP CHIP 0402 2.2uF 6.3V X5R 10%", Case Code (Imperial)=0402, Case Code (Metric)=1005, Dielectric=X5R, Manufacturer=Murata, Tolerance=10%, Voltage=6.3V
C4V C5V: library part C0037-A.9, "CAP CHIP 0402 4.7uF 6V3 X5R 20%", Case Code (Imperial)=0402, Case Code (Metric)=1005, Dielectric=X5R, Manufacturer=Murata, Tolerance=20%, Voltage=6.3V
C7 C8 C9 C10 C13 C15 C16 C17 C18 C19 C20 C21 C22 C23 C24 C28 C29 C36 C37 C41 C42 C51 C52 C53 C73 C75 C76 C77 C78: library part C0015-A.9, "CAP CHIP 0402 100nF 50V X5R 10%", Case Code (Imperial)=0402, Case Code (Metric)=1005, Dielectric=X5R, Manufacturer=Murata, Tolerance=10%, Voltage=50V
C24 C28 C31 C33 C49: library part C0017-A.9, "CAP CHIP 0402 1uF 10V X5R 10%", Case Code (Imperial)=0402, Case Code (Metric)=1005, Dielectric=X5R, Manufacturer=KEMET, Manufacturer 2=AVX, Manufacturer Part Number 2=GRM155R61A105KE15D, Tolerance=10%, Voltage=10V
C25 C26 C27 C35 C36 C37 C43 C48 C51: library part C0012-A.9, "CAP CHIP 0402 100nF 16V X7R 10%", Case Code (Imperial)=0402, Case Code (Metric)=1005, Dielectric=X7R, Manufacturer=KEMET, Manufacturer 2=AVX, Manufacturer Part Number 2=0402YC104KAT2A, Tolerance=10%, Voltage=16V
C46 C50: library part C0074-A.7, "CAP CHIP 0402 150PF 50V C0G 1%", Case Code (Imperial)=0402, Case Code (Metric)=1005, Dielectric=C0G, Manufacturer=Murata, Tolerance=1%, Voltage=50V
J1: library part J0169-A.5
J1V: library part J0042-A.4, "CONN Micro UFL NO PASTE", Manufacturer=Hirose
J2 J3 J6 J7 J8: library part J0171-A.2
J4: library part J0239-A.1
J5: library part J0240-A.2
J9: library part J0081-A.3, "CONN FPC VERT 20POS 1.00MM SMD", Contact Current Rating=1A, Flammability Rating="UL94 V-0", Housing Color=Black, Manufacturer="TE Connectivity", Max Operating Temperature=185°C, Min Operating Temperature=-4°C, Package Quantity=1000, Voltage Rating=125V
J10 J11: library part J0220-A.5, "CONN RCP USB3.1 TYPEC 24P SMD RA", Flammability Rating="UL94 V-0", Manufacturer="Amphenol ICC (Commercial Products)"
J12: library part J0089-A.6, "CONN HEADER SMD 10POS 2x5 1.27MM JTAG", Color=Black, Current Rating=1.75A, Manufacturer=Samtec, Max Operating Temperature=125°C, Min Operating Temperature=-55°C, Package Quantity=1
J13 J14 J17 J18: library part J0245-A.1
J19: library part J0244-A.1, "Conn Jack 4 POLES 3.5mm R/a", Manufacturer="Tensility International Corp"
J20: library part J0162-A.4
L1: library part I0004-A.3, "FERRITE SMD 0603 18 OHM 1A", Case Code (Imperial)=0603, Case Code (Metric)=1608, Current=1A, DC Resistance (DCR)=4mR, Manufacturer="Taiyo Yuden", Max DC Current=7.5A, Max Operating Temperature=125°C, Min Operating Temperature=-40°C, Package Quantity=1, Test Frequency=100MHz, Tolerance=30%
L1V: library part I0051-A.3, "IND FIXED SMD 0603 2.2uH, 20%,", DC Resistance (DCR)=250mR, Manufacturer=Murata, Max Operating Temperature=85°C, Min Operating Temperature=-40°C, Test Frequency=1MHz, Tolerance=20%
PB1 PB2: library part B0006-A.7, "PUSHBUTTON SMD PTS820 NO HOLES", Color=Black, Manufacturer=C&K, Max Operating Temperature=85°C, Min Operating Temperature=-40°C
R1 R4 R6 R48: library part R0001-A.8, "RES CHIP 0402 100K 1% 1/16W", Case Code (Imperial)=0402, Case Code (Metric)=1005, Manufacturer=Vishay, Manufacturer 2=Panasonic, Manufacturer Part Number 2=ERJ-2RKF1003X, Power=63mW, Tolerance=1%
R1V R3 R7 R8 R44 R45: library part R0000-A.8, "RES CHIP 0402 0R 1/16W", Case Code (Imperial)=0402, Case Code (Metric)=1005, Manufacturer=Vishay, Manufacturer 2=Panasonic, Manufacturer Part Number 2=ERJ-S020R00X, Power=63mW, Tolerance=J
R2: library part R0154-A.2, "RES CHIP 0201 8.06kR 1/20W 1%", Case Code (Imperial)=0201, Case Code (Metric)=0603, Manufacturer=Yageo, Power=50mW, Tolerance=1%
R9 R10 R11 R12: library part R0131-A.3, "RES CHIP 0805 0R 1/8W", Case Code (Imperial)=0805, Case Code (Metric)=2012, Manufacturer=Vishay, Power=125mW, Tolerance=J
R34 R35: library part R0166-A.4, "RES CHIP 0402 2K 5% 1/16W", Case Code (Imperial)=0402, Case Code (Metric)=1005, Manufacturer=Vishay, Manufacturer 2=Panasonic, Manufacturer Part Number 2=ERJ-2GEJ202X, Power=63mW, Tolerance=1%
R46: library part R0003-A.8, "RES CHIP 0402 10K 1% 1/16W", Case Code (Imperial)=0402, Case Code (Metric)=1005, Manufacturer=Vishay, Manufacturer 2=Panasonic, Manufacturer Part Number 2=ERJ-2RKF1002X, Power=63mW, Tolerance=1%
U1: library part U0020-A.5, "IC MCU Cortex M7 + Cortex M4", Manufacturer=STMicroelectronics
U1V: library part U0008-A.14, "MODULE WiFi 11b/g/n+BLUETOOTH 4.2 SHIELDED ULTRA SMALL LBEE5KL1DX", Case/Package=SMD/SMT, Current - Receiving=60mA, Current - Transmitting=370mA, Frequency=2.4GHz, Manufacturer=Murata, Max Operating Temperature=70°C, Min Operating Temperature=-30°C
U2: library part U0122-A.2, "IC SDRAM 64 Mb PC133 SDR", Case/Package=TFBGA, Frequency=166MHz, Manufacturer="Alliance Memory", Max Operating Temperature=85°C, Min Operating Temperature=-40°C
U2: library part U0053-A.4, "IC CODEC STER HDPN & SPKR 40QFN", Case/Package=QFN, Manufacturer="Cirrus Logic", Max Operating Temperature=85°C, Min Operating Temperature=-40°C, Operating Supply Voltage=2.5V, Package Quantity=50
U3: library part U0121-A.4, "IC TXRX USB 2.0 FLEXPWR 32QFN", Case/Package=QFN, Frequency=60MHz, Manufacturer=Microchip, Max Operating Temperature=85°C, Max Supply Voltage=2V, Min Operating Temperature=-40°C, Min Supply Voltage=1.6V, Operating Supply Current=18uA, Operating Supply Voltage=5.5V, Package Quantity=4000
U4: library part U0120-A.2, "IC FLASH S-NOR 128M", Manufacturer=Macronix

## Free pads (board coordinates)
  round 3.2 hole 3.2 unplated: MH1(96.52,2.54) MH2(15.24,50.8) MH3(90.17,50.8) MH4(13.996,2.553) MH5(66.04,35.56) MH6(66.066,7.633)

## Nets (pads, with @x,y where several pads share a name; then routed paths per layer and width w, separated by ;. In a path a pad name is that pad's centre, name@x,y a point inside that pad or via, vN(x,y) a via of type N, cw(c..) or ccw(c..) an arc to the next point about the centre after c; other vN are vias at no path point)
+1V8: U1V.36
+3V1: 
+3V1SW: 
+3V3: C3V.2 C4V.1 U1V.30
AIN2A: 
AIN2B: 
AIN3A: 
AIN3B: 
BLE_CTRL_DEVICE_WAKE: U1V.39
BLE_CTRL_HOST_WAKE: U1V.38
BLE_CTRL_ON: U1V.14
DSI_CK_N: 
DSI_CK_P: 
DSI_D0_N: 
DSI_D0_P: 
DSI_D1_N: 
DSI_D1_P: 
GND: C1V.2 C2V.2 C3V.1 C4V.2 C5V.2 J1V.GND U1V.1 U1V.12 U1V.19 U1V.21 U1V.29 U1V.32 U1V.33 U1V.35 U1V.40 U1V.42 U1V.43 U1V.44 U1V.45 U1V.46
HP/LINE_OUTA: 
HP/LINE_OUTB: 
HSU_D_N: 
HSU_D_P: 
MICBIAS: 
NetAUDIO_RST_X: 
NetC1_2: 
NetC1V_1: C1V.1 R1V.1 U1V.41 | length 5.8
  TOP w0.5: R1V.1 C1V.1 10.839,46.6 cw(c10.839,46.23) 11.209,46.23
NetC2V_1: C2V.1 J1V.SIG R1V.2 | length 3.6
  TOP w0.5: J1V.SIG 2.6,47.1 ccw(c3.1,47.1) 3.1,46.6 C2V.1 R1V.2
NetC5V_1: C5V.1 L1V.2 U1V.31
NetC12_2: 
NetC30_2: 
NetC31_1: 
NetC31_2: 
NetC33_1: 
NetC46_1: 
NetC48_1: 
NetC49_1: 
NetC50_1: 
NetL1_2: 
NetL1V_1: L1V.1 U1V.34
NetR2_1: 
NetR3_1: 
NetR4_2: 
NetR6_1: 
NetR7_1: 
NetR8_2: 
NetR9_1: 
NetR10_2: 
NetR12_1: 
NetR34_2: 
NetR35_2: 
NetR46_1: 
NetR46_2: 
NetU1_J1: 
NetU1_K1: 
NetU1V_2: U1V.2
NetU1V_3: U1V.3
NetU1V_4: U1V.4
NetU1V_5: U1V.5
NetU1V_8: U1V.8
NetU1V_9: U1V.9
NetU1V_10: U1V.10
NetU1V_11: U1V.11
NetU1V_20: U1V.20
NetU1V_22: U1V.22
NetU1V_23: U1V.23
NetU1V_24: U1V.24
NetU1V_25: U1V.25
NetU1V_26: U1V.26
NetU1V_37: U1V.37
NetU2_37: 
NetU3_26: 
PA0: 
PA1: 
PA2: 
PA3: 
PA4: 
PA5: 
PA6: 
PA7: 
PA8: 
PA9: 
PA10: 
PA11: 
PA12: 
PA13: 
PA14: 
PA15: 
PB0: 
PB1: 
PB2: 
PB3: 
PB4: 
PB5: 
PB6: 
PB7: 
PB8: 
PB9: 
PB10: 
PB11: 
PB12: 
PB13: 
PB14: 
PB15: 
PC0: 
PC1: 
PC2: 
PC3: 
PC4: 
PC5: 
PC6: 
PC7: 
PC8: 
PC9: 
PC10: 
PC11: 
PC12: 
PC13: 
PD0: 
PD1: 
PD2: 
PD3: 
PD4: 
PD5: 
PD6: 
PD7: 
PD8: 
PD9: 
PD10: 
PD11: 
PD12: 
PD13: 
PD14: 
PD15: 
PE0: 
PE1: 
PE2: 
PE3: 
PE4: 
PE5: 
PE6: 
PE7: 
PE8: 
PE9: 
PE10: 
PE11: 
PE12: 
PE13: 
PE14: 
PE15: 
PF0: 
PF1: 
PF2: 
PF3: 
PF4: 
PF5: 
PF6: 
PF7: 
PF8: 
PF9: 
PF10: 
PF11: 
PF12: 
PF13: 
PF14: 
PF15: 
PG0: 
PG1: 
PG2: 
PG3: 
PG4: 
PG5: 
PG6: 
PG7: 
PG8: 
PG9: 
PG10: 
PG11: 
PG12: 
PG13: 
PG14: 
PG15: 
PH2: 
PH3: 
PH4: 
PH5: 
PH6: 
PH7: 
PH8: 
PH9: 
PH10: 
PH11: 
PH12: 
PH13: 
PH14: 
PH15: 
PI0: 
PI1: 
PI2: 
PI3: 
PI4: 
PI5: 
PI6: 
PI7: 
PI8: 
PI9: 
PI10: 
PI11: 
PI12: 
PI13: 
PI14: 
PI15: 
PJ0: 
PJ1: 
PJ2: 
PJ3: 
PJ4: 
PJ5: 
PJ6: 
PJ7: 
PJ8: 
PJ9: 
PJ10: 
PJ11: 
PJ12: 
PJ13: 
PJ14: 
PJ15: 
PK0: 
PK1: 
PK2: 
PK3: 
PK4: 
PK5: 
PK6: 
PK7: 
SPKR/HP: 
USB0_D_N: 
USB0_D_P: 
VCAP_A7: 
VCAP_D17: 
VCAP_U11: 
WIFI_CTRL_HOST_WAKE: U1V.27
WIFI_CTRL_ON: U1V.28
pads on no net: "J10.SHIELD 1" "J10.SHIELD 2" "J10.SHIELD 3" "J10.SHIELD 4" "J11.SHIELD 1" "J11.SHIELD 2" "J11.SHIELD 3" "J11.SHIELD 4" AUDIO_RST.X C1.1 C1.2 C3.1 C3.2 C4.1 C4.2 C5.1 C5.2 C6.1 C6.2 C7.1 C7.2 C8.1 C8.2 C9.1 C9.2 C10.1 C10.2 C12.1 C12.2 C13.1 C13.2 C15.1 C15.2 C16.1 C16.2 C17.1 C17.2 C18.1 C18.2 C19.1 C19.2 C20.1 C20.2 C21.1 C21.2 C22.1 C22.2 C23.1 C23.2 C24.1 C24.2 C25.1 C25.2 C26.1 C26.2 C27.1 C27.2 C28.1 C28.2 C29.1 C29.2 C30.1 C30.2 C31.1 C31.2 C33.1 C33.2 C35.1 C35.2 C36.1 C36.2 C37.1 C37.2 C41.1 C41.2 C42.1 C42.2 C43.1 C43.2 C46.1 C46.2 C48.1 C48.2 C49.1 C49.2 C50.1 C50.2 C51.1 C51.2 C52.1 C52.2 C53.1 C53.2 C73.1 C73.2 C75.1 C75.2 C76.1 C76.2 C77.1 C77.2 C78.1 C78.2 J1.1 J1.2 J1.3 J1.4 J1.5 J1.6 J1.7 J1.8 J1.9 J1.10 J2.1 J2.2 J2.3 J2.4 J2.5 J2.6 J2.7 J2.8 J3.1 J3.2 J3.3 J3.4 J3.5 J3.6 J3.7 J3.8 J4.1 J4.2 J4.3 J4.4 J4.5 J4.6 J4.7 J4.8 J4.9 J4.10 J4.11 J4.12 J4.13 J4.14 J4.15 J4.16 J4.17 J4.18 J4.19 J4.20 J4.21 J4.22 J4.23 J4.24 J4.25 J4.26 J4.27 J4.28 J4.29 J4.30 J4.31 J4.32 J4.33 J4.34 J4.35 J4.36 J5.1 J5.2 J5.3 J5.4 J5.5 J5.6 J6.1 J6.2 J6.3 J6.4 J6.5 J6.6 J6.7 J6.8 J7.1 J7.2 J7.3 J7.4 J7.5 J7.6 J7.7 J7.8 J8.1 J8.2 J8.3 J8.4 J8.5 J8.6 J8.7 J8.8 J9.1 J9.2 J9.3 J9.4 J9.5 J9.6 J9.7 J9.8 J9.9 J9.10 J9.11 J9.12 J9.13 J9.14 J9.15 J9.16 J9.17 J9.18 J9.19 J9.20 J9.21 J9.22 J9.23 J9.24 J9.25 J9.26 J9.27 J9.28 J9.29 J9.30 J9.31 J9.32 J9.33 J9.34 J9.35 J9.36 J9.37 J9.38 J9.39 J9.40 J10.0 J10.A1 J10.A2 J10.A3 J10.A4 J10.A5 J10.A6 J10.A7 J10.A8 J10.A9 J10.A10 J10.A11 J10.A12 J10.B1 J10.B2 J10.B3 J10.B4 J10.B5 J10.B6 J10.B7 J10.B8 J10.B9 J10.B10 J10.B11 J10.B12 J11.0 J11.A1 J11.A2 J11.A3 J11.A4 J11.A5 J11.A6 J11.A7 J11.A8 J11.A9 J11.A10 J11.A11 J11.A12 J11.B1 J11.B2 J11.B3 J11.B4 J11.B5 J11.B6 J11.B7 J11.B8 J11.B9 J11.B10 J11.B11 J11.B12 J12.1 J12.2 J12.3 J12.4 J12.5 J12.6 J12.7 J12.8 J12.9 J12.10 J13.1 J13.2 J13.3 J13.4 J13.5 J13.6 J13.7 J13.8 J13.9 J13.10 J13.11 J13.12 J13.13 J14.1 J14.2 J14.3 J14.4 J14.5 J14.6 J14.7 J14.8 J14.9 J14.10 J14.11 J14.12 J14.13 J17.1 J17.2 J17.3 J17.4 J17.5 J17.6 J17.7 J17.8 J17.9 J17.10 J17.11 J17.12 J17.13 J18.1 J18.2 J18.3 J18.4 J18.5 J18.6 J18.7 J18.8 J18.9 J18.10 J18.11 J18.12 J18.13 J19.1 J19.2 J19.3 J19.4 J19.NC1 J19.NC2 J20.1 J20.2 J20.3 J20.4 L1.1 L1.2 PB1.5 PB1.6 PB1.PAD PB2.5 PB2.6 PB2.PAD R1.1 R1.2 R2.1 R2.2 R3.1 R3.2 R4.1 R4.2 R6.1 R6.2 R7.1 R7.2 R8.1 R8.2 R9.1 R9.2 R10.1 R10.2 R11.1 R11.2 R12.1 R12.2 R34.1 R34.2 R35.1 R35.2 R44.1 R44.2 R45.1 R45.2 R46.1 R46.2 R48.1 R48.2 U1.A1 U1.A2 U1.A3 U1.A4 U1.A5 U1.A6 U1.A7 U1.A8 U1.A9 U1.A10 U1.A11 U1.A12 U1.A13 U1.A14 U1.A15 U1.A16 U1.A17 U1.B1 U1.B2 U1.B3 U1.B4 U1.B5 U1.B6 U1.B7 U1.B8 U1.B9 U1.B10 U1.B11 U1.B12 U1.B13 U1.B14 U1.B15 U1.B16 U1.B17 U1.C1 U1.C2 U1.C3 U1.C4 U1.C5 U1.C6 U1.C7 U1.C8 U1.C9 U1.C10 U1.C11 U1.C12 U1.C13 U1.C14 U1.C15 U1.C16 U1.C17 U1.D1 U1.D2 U1.D3 U1.D4 U1.D5 U1.D6 U1.D7 U1.D8 U1.D9 U1.D10 U1.D11 U1.D12 U1.D13 U1.D14 U1.D15 U1.D16 U1.D17 U1.E1 U1.E2 U1.E3 U1.E4 U1.E5 U1.E6 U1.E7 U1.E8 U1.E9 U1.E10 U1.E11 U1.E12 U1.E13 U1.E14 U1.E15 U1.E16 U1.E17 U1.F1 U1.F2 U1.F3 U1.F4 U1.F5 U1.F13 U1.F14 U1.F15 U1.F16 U1.F17 U1.G1 U1.G2 U1.G3 U1.G4 U1.G5 U1.G7 U1.G8 U1.G9 U1.G10 U1.G11 U1.G13 U1.G14 U1.G15 U1.G16 U1.G17 U1.H1 U1.H2 U1.H3 U1.H4 U1.H5 U1.H7 U1.H8 U1.H9 U1.H10 U1.H11 U1.H13 U1.H14 U1.H15 U1.H16 U1.H17 U1.J1 U1.J2 U1.J3 U1.J4 U1.J5 U1.J7 U1.J8 U1.J9 U1.J10 U1.J11 U1.J13 U1.J14 U1.J15 U1.J16 U1.J17 U1.K1 U1.K2 U1.K3 U1.K4 U1.K5 U1.K7 U1.K8 U1.K9 U1.K10 U1.K11 U1.K13 U1.K14 U1.K15 U1.K16 U1.K17 U1.L1 U1.L2 U1.L3 U1.L4 U1.L5 U1.L7 U1.L8 U1.L9 U1.L10 U1.L11 U1.L13 U1.L14 U1.L15 U1.L16 U1.L17 U1.M1 U1.M2 U1.M3 U1.M4 U1.M5 U1.M13 U1.M14 U1.M15 U1.M16 U1.M17 U1.N1 U1.N2 U1.N3 U1.N4 U1.N5 U1.N6 U1.N7 U1.N8 U1.N9 U1.N10 U1.N11 U1.N12 U1.N13 U1.N14 U1.N15 U1.N16 U1.N17 U1.P1 U1.P2 U1.P3 U1.P4 U1.P5 U1.P6 U1.P7 U1.P8 U1.P9 U1.P10 U1.P11 U1.P12 U1.P13 U1.P14 U1.P15 U1.P16 U1.P17 U1.R1 U1.R2 U1.R3 U1.R4 U1.R5 U1.R6 U1.R7 U1.R8 U1.R9 U1.R10 U1.R11 U1.R12 U1.R13 U1.R14 U1.R15 U1.R16 U1.R17 U1.T1 U1.T2 U1.T3 U1.T4 U1.T5 U1.T6 U1.T7 U1.T8 U1.T9 U1.T10 U1.T11 U1.T12 U1.T13 U1.T14 U1.T15 U1.T16 U1.T17 U1.U1 U1.U2 U1.U3 U1.U4 U1.U5 U1.U6 U1.U7 U1.U8 U1.U9 U1.U10 U1.U11 U1.U12 U1.U13 U1.U14 U1.U15 U1.U16 U1.U17 U1V.6 U1V.7 U1V.13 U1V.15 U1V.16 U1V.17 U1V.18 U2.1 U2.2 U2.3 U2.4 U2.5 U2.6 U2.7 U2.8 U2.9 U2.10 U2.11 U2.12 U2.13 U2.14 U2.15 U2.16 U2.17 U2.18 U2.19 U2.20 U2.21 U2.22 U2.23 U2.24 U2.25 U2.26 U2.27 U2.28 U2.29 U2.30 U2.31 U2.32 U2.33 U2.34 U2.35 U2.36 U2.37 U2.38 U2.39 U2.40 U2.41 U2.A1 U2.A2 U2.A3 U2.A7 U2.A8 U2.A9 U2.B1 U2.B2 U2.B3 U2.B7 U2.B8 U2.B9 U2.C1 U2.C2 U2.C3 U2.C7 U2.C8 U2.C9 U2.D1 U2.D2 U2.D3 U2.D7 U2.D8 U2.D9 U2.E1 U2.E2 U2.E3 U2.E7 U2.E8 U2.E9 U2.F1 U2.F2 U2.F3 U2.F7 U2.F8 U2.F9 U2.G1 U2.G2 U2.G3 U2.G7 U2.G8 U2.G9 U2.H1 U2.H2 U2.H3 U2.H7 U2.H8 U2.H9 U2.J1 U2.J2 U2.J3 U2.J7 U2.J8 U2.J9 U3.1 U3.2 U3.3 U3.4 U3.5 U3.6 U3.7 U3.8 U3.9 U3.10 U3.11 U3.12 U3.13 U3.14 U3.15 U3.16 U3.17 U3.18 U3.19 U3.20 U3.21 U3.22 U3.23 U3.24 U3.25 U3.26 U3.27 U3.28 U3.29 U3.30 U3.31 U3.32 U3.33 U4.1 U4.2 U4.3 U4.4 U4.5 U4.6 U4.7 U4.8 U4.9

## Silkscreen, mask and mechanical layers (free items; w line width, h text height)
Top Overlay:
  drawing of 40 lines, arcs and shapes, not listed
  text "WIFI" at -0.077,51.865 h1.5
  text "RESET" at 6.423,51.865 h1.5
  text "22" at 90.57,47.494 h1.8
  text "13" at 29.747,47.279 h1.8 r90
  text "7" at 46.485,47.083 h1.8 r90
  text "6" at 49.025,47.083 h1.8 r90
  text "5" at 51.565,47.083 h1.8 r90
  text "4" at 54.105,47.083 h1.8 r90
  text "3" at 56.645,47.083 h1.8 r90
  text "2" at 59.185,47.083 h1.8 r90
  text "1" at 61.725,47.083 h1.8 r90
  text "0" at 64.265,47.083 h1.8 r90
  text "14" at 69.345,47.083 h1.8 r90
  text "15" at 71.885,47.083 h1.8 r90
  text "16" at 74.425,47.083 h1.8 r90
  text "17" at 76.965,47.083 h1.8 r90
  text "18" at 79.505,47.083 h1.8 r90
  text "19" at 82.045,47.083 h1.8 r90
  text "20" at 84.585,47.083 h1.8 r90
  text "21" at 87.125,47.083 h1.8 r90
  text "12" at 32.214,45.282 h1.8 r90
  text "SCL1" at 19.514,45.098 h1.8 r90
  text "11" at 34.754,45.103 h1.8 r90
  text "10" at 37.294,45.103 h1.8 r90
  text "9" at 39.834,45.103 h1.8 r90
  text "8" at 42.374,45.103 h1.8 r90
  text "24" at 90.57,44.954 h1.8
  text "SDA1" at 22.054,44.918 h1.8 r90
  text "GND" at 27.192,44.897 h1.8 r90
  text "AREF" at 24.594,44.587 h1.8 r90
  text "26" at 90.57,42.414 h1.8
  text "54" at 70.25,39.874 h1.8
  text "55" at 77.87,39.874 h1.8
  text "56" at 80.41,39.874 h1.8
  text "57" at 88,39.874 h1.8
  text "28" at 90.57,39.874 h1.8
  text "GND" at 76.2,37.349 h1.8
  text "58" at 70.25,37.334 h1.8
  text "59" at 88,37.334 h1.8
  text "30" at 90.57,37.334 h1.8
  text "31" at 98.19,37.334 h1.8
  text "63" at 88,35.047 h1.8
  text "60" at 70.25,34.794 h1.8
  text "61" at 77.87,34.794 h1.8
  text "62" at 80.41,34.794 h1.8
  text "32" at 90.57,34.794 h1.8
  text "33" at 98.19,34.794 h1.8
  text "GND" at 76.2,32.269 h1.8
  text "64" at 70.25,32.254 h1.8
  text "65" at 88,32.254 h1.8
  text "34" at 90.57,32.254 h1.8
  text "35" at 98.19,32.254 h1.8
  text "66" at 70.25,29.714 h1.8
  text "68" at 77.87,29.714 h1.8
  text "67" at 80.41,29.714 h1.8
  text "69" at 88,29.714 h1.8
  text "36" at 90.57,29.714 h1.8
  text "37" at 98.19,29.714 h1.8
  text "GND" at 76.2,27.189 h1.8
  text "70" at 70.25,27.174 h1.8
  text "71" at 88,27.174 h1.8
  text "38" at 90.57,27.174 h1.8
  text "39" at 98.19,27.174 h1.8
  text "72" at 70.25,24.634 h1.8
  text "73" at 77.87,24.634 h1.8
  text "74" at 80.41,24.634 h1.8
  text "75" at 88,24.634 h1.8
  text "40" at 90.57,24.634 h1.8
  text "41" at 98.19,24.634 h1.8
  text "GND" at 76.2,22.109 h1.8
  text "76" at 70.25,22.094 h1.8
  text "77" at 88,22.094 h1.8
  text "42" at 90.57,22.094 h1.8
  text "43" at 98.19,22.094 h1.8
  text "78" at 70.25,19.554 h1.8
  text "79" at 77.87,19.554 h1.8
  text "80" at 80.41,19.554 h1.8
  text "81" at 88,19.554 h1.8
  text "44" at 90.57,19.554 h1.8
  text "45" at 98.19,19.554 h1.8
  text "GND" at 76.2,17.029 h1.8
  text "82" at 70.25,17.014 h1.8
  text "83" at 88,17.014 h1.8
  text "46" at 90.57,17.014 h1.8
  text "47" at 98.19,17.014 h1.8
  text "BOOT0" at 62.093,16.873 h1.8
  text "84" at 70.25,14.474 h1.8
  text "85" at 77.87,14.474 h1.8
  text "86" at 80.41,14.474 h1.8
  text "87" at 88,14.474 h1.8
  text "48" at 90.57,14.474 h1.8
  text "49" at 98.19,14.474 h1.8
  text "GIGA" at 59.199,13.497 h4
  text "GND" at 76.2,11.949 h1.8
  text "88" at 70.25,11.934 h1.8
  text "89" at 88,11.934 h1.8
  text "50" at 90.57,11.934 h1.8
  text "51" at 98.19,11.934 h1.8
  text "90" at 70.25,9.394 h1.8
  text "91" at 77.87,9.394 h1.8
  text "92" at 80.41,9.394 h1.8
  text "93" at 88,9.394 h1.8
  text "52" at 90.57,9.394 h1.8
  text "53" at 98.19,9.394 h1.8
  text "GND" at 93.98,6.869 h1.6
  text "SPKA+" at 18.545,4.349 h1.8 r90
  text "SPKA-" at 21.085,4.349 h1.8 r90
  text "SPKB+" at 23.625,4.349 h1.8 r90
  text "SPKB-" at 26.165,4.349 h1.8 r90
  text "NTC VBAT" at 29.243,4.349 h1.8 r90
  text "IOREF" at 31.245,4.349 h1.8 r90
  text "RESET" at 33.785,4.349 h1.8 r90
  text "3V3" at 36.325,4.349 h1.8 r90
  text "5V" at 38.865,4.349 h1.8 r90
  text "VIN" at 46.485,4.349 h1.8 r90
  text "A0" at 51.565,4.349 h1.8 r90
  text "A1" at 54.105,4.349 h1.8 r90
  text "A2" at 56.645,4.349 h1.8 r90
  text "A3" at 59.185,4.349 h1.8 r90
  text "A4" at 61.725,4.349 h1.8 r90
  text "A5" at 64.265,4.349 h1.8 r90
  text "A6" at 66.805,4.349 h1.4 r90
  text "A7" at 69.345,4.349 h1.8 r90
  text "A8" at 74.425,4.349 h1.8 r90
  text "A9" at 76.965,4.349 h1.8 r90
  text "A10" at 79.505,4.349 h1.8 r90
  text "A11" at 82.045,4.349 h1.8 r90
  text "DAC2" at 84.585,4.349 h1.8 r90
  text "DAC1" at 87.125,4.349 h1.8 r90
  text "CANRX" at 89.665,4.349 h1.5 r90
  text "CANTX" at 92.205,4.349 h1.5 r90
  text "GND" at 41.416,2.553 h1.8 r90
  text "GND" at 43.956,2.553 h1.8 r90
  text "AUDIO IN/OUT" at 0.331,0.291 h1.8
Route Tool Path:
  lines w2: -1,29.75 -1,22.47 -1,1 ccw(c1,1) 1,-1 42.3,-1 48.8,-1 ; -1,33.75 -1,40.25 -1,52.34 cw(c1,52.34) 1,54.34 41.52,54.34 48.8,54.34 ; 52.8,-1 60.08,-1 98.06,-1 ccw(c98.06,1) 100.06,1 100.06,2.126 102.307,4.373 ; 52.8,54.34 59.3,54.34 97.536,54.34 ; 102.6,19.096 102.6,12.596 102.6,5.08 ; 102.6,23.096 102.6,30.376 102.6,37.846 ; 97.536,54.34 cw(c97.536,53.34) 98.243,54.047 ; 97.536,54.34 cw(c97.536,53.34) 98.243,54.047 ; 98.243,54.047 99.767,52.523 ; 99.767,52.523 cw(c99.06,51.816) 100.06,51.816 ; 99.767,52.523 cw(c99.06,51.816) 100.06,51.816 ; 100.06,51.816 100.06,40.8 102.307,38.553 ; 102.307,4.373 ccw(c101.6,5.08) 102.6,5.08 ; 102.307,4.373 ccw(c101.6,5.08) 102.6,5.08 ; 102.307,38.553 cw(c101.6,37.846) 102.6,37.846 ; 102.307,38.553 cw(c101.6,37.846) 102.6,37.846
Board:
  the board outline again, w0.254
Mechanical 9:
  lines w0.1: 6.194,2.927 7.464,2.927 ; 7.464,1.657 7.464,2.927 ; 7.464,4.197 7.464,2.927 ; 8.734,2.927 7.464,2.927 ; 17.552,50.813 18.822,50.813 ; 18.822,49.543 18.822,50.813 ; 18.822,52.083 18.822,50.813 ; 20.092,50.813 18.822,50.813 ; 26.696,2.553 27.966,2.553 ; 27.966,1.283 27.966,2.553 ; 27.966,3.823 27.966,2.553 ; 29.236,2.553 27.966,2.553 ; 44.476,50.813 45.746,50.813 ; 45.746,49.543 45.746,50.813 ; 45.746,52.083 45.746,50.813 ; 47.016,50.813 45.746,50.813 ; 49.556,2.553 50.826,2.553 ; 50.826,1.283 50.826,2.553 ; 50.826,3.823 50.826,2.553 ; 52.096,2.553 50.826,2.553 ; 62.357,30.48 63.627,30.48 ; 63.627,29.21 63.627,30.48 ; 63.627,31.75 63.627,30.48 ; 64.897,30.48 63.627,30.48 ; 67.336,50.813 68.606,50.813 ; 68.606,49.543 68.606,50.813 ; 68.606,52.083 68.606,50.813 ; 69.876,50.813 68.606,50.813 ; 72.416,2.553 73.686,2.553 ; 73.686,1.283 73.686,2.553 ; 73.686,3.823 73.686,2.553 ; 74.956,2.553 73.686,2.553 ; 92.71,50.799 93.98,50.799 ; 93.98,49.529 93.98,50.799 ; 93.98,52.069 93.98,50.799 ; 95.25,50.799 93.98,50.799
Top Assembly:
  lines w0.15: -13.69,12.13 -3.69,12.13 -3.69,32.13 -13.69,32.13 -13.69,12.13 ; -11.19,32.7 -11.19,47.7 -3.69,47.7 -3.69,32.7 -11.19,32.7 ; -8.69,-0.07 -3.69,-0.07 -3.69,9.93 -8.69,9.93 -8.69,-0.07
